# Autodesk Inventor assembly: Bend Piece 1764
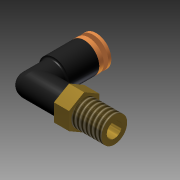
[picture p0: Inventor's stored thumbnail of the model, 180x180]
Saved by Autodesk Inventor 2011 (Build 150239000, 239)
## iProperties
Created: 2010-02
Part Number: Bend Piece 1764
Document SubType Name: Assembly
Designer: jgehrig
Author: jgehrig
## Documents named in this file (4)
- R:\CAD Archives\Pnewmatics\Seloniod 1764\Pnewmatics Bend Piece 1764\Pnewmatic Bend Piece 1764.iam
- R:\CAD Archives\Pnewmatics\Seloniod 1764\Pnewmatics Bend Piece 1764\Pnematic Screw Part 1764.ipt
- R:\CAD Archives\Pnewmatics\Seloniod 1764\Pnewmatics Bend Piece 1764\Pnewmatic Screw Part 2 1764.ipt
- R:\CAD Archives\Pnewmatics\Pnewmatics Bend Piece 1764\Pnewmatic Bend Piece 1764.ipt
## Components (3 placed, 3 different names)
1. Pnewmatic Bend Piece 1764:1 — Insert:1, Insert:2
2. Pnematic Screw Part 1764:1 — Insert:2
3. Pnewmatic Screw Part 2 1764:1 — Insert:1
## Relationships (2: Insert 2)
- Insert:1: Pnewmatic Bend Piece 1764:1 ↔ Pnewmatic Screw Part 2 1764:1
- Insert:2: Pnewmatic Bend Piece 1764:1 ↔ Pnematic Screw Part 1764:1
